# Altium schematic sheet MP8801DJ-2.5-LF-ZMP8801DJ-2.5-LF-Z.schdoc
size 127 x 101 mm
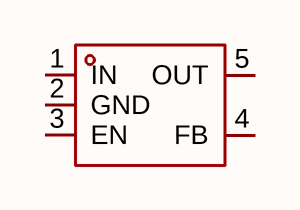
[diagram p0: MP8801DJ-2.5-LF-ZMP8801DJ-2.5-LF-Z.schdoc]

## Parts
U?  mp8801dj-2.5-lf-z  [SOT-23-5_L2.9-W1.6-P0.95-LS2.8-BR]  (value not drawn)

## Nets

Not connected (* = marked no-connect by the designer): U? 1(IN) 2(GND) 3(EN) 4(FB) 5(OUT)

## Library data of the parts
U? = mp8801dj-2.5-lf-z: 输出极性:正极;工作电压:6.5V;输出电压:2.5V；1.25V~5V;输出电流:150mA;电源纹波抑制比(PSRR):70dB@(1kHz);输出类型:固定；可调;; Manufacturer: MPS(芯源); AddInBom: yes; ModelId: 7ba65df16e7b4570af156e925f9c37fe; ModelTransform: 114.173,114.173,0,90,0,0,0,0,0; Output Configuration: 正极; Voltage - Supply: 6.5V; Output Current: 150mA; Voltage Dropout: 150mV@(150mA); standby current: 125uA; Output Type: 固定；可调; Number of Outputs: 1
